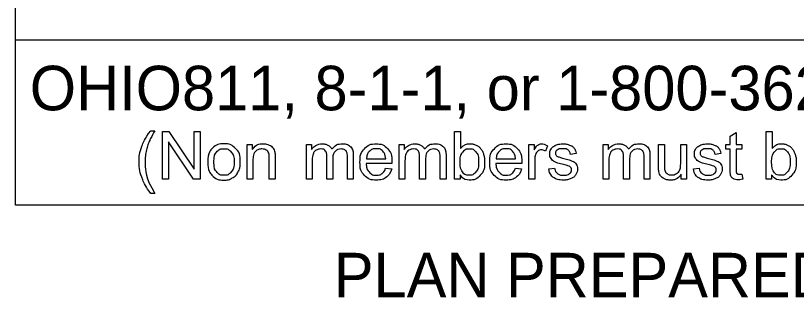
# Model space of a CAD drawing. Extents: x 0 to 2329303, y 0 to 694397.
# Drawn here: x 3 to 5.454, y 2.68 to 3.565 of the extents above; entities that cross this region are included whole.
import ezdxf

# ---------------------------------------------------------------- set-up
doc = ezdxf.new("R2010")
doc.units = 0
doc.layers.add('SH_Data', color=7, linetype='Continuous')

msp = doc.modelspace()

# ---------------------------------------------------------------- linework, layer by layer
at = {"layer": 'SH_Data'}
for p, q in [((3, 2.97), (3, 5.3075)), ((7.25, 3.4878), (3, 3.4878)), ((7.25, 2.97), (3, 2.97))]:
    msp.add_line(p, q, dxfattribs=at)
for points in [[(3.4246, 3.2038), (3.4378, 3.2038)], [(3.4614, 3.0511), (3.4614, 3.2013), (3.4817, 3.2013), (3.5607, 3.0833), (3.5607, 3.2013), (3.5797, 3.2013), (3.5797, 3.0511), (3.5594, 3.0511), (3.4804, 3.169), (3.4804, 3.0511), (3.4614, 3.0511)], [(4.3968, 3.0511), (4.3798, 3.0511), (4.3798, 3.2013), (4.3982, 3.2013), (4.3982, 3.1477)], [(5.2458, 3.083), (5.2458, 3.1456), (5.2321, 3.1456), (5.2321, 3.1599), (5.2458, 3.1599), (5.2458, 3.1869), (5.2642, 3.1979), (5.2642, 3.1599), (5.2826, 3.1599), (5.2826, 3.1456), (5.2642, 3.1456), (5.2642, 3.0819)], [(5.3759, 3.0511), (5.3588, 3.0511), (5.3588, 3.2013), (5.3773, 3.2013), (5.3773, 3.1477)], [(3.7273, 3.0511), (3.7273, 3.1599), (3.7439, 3.1599), (3.7439, 3.1445)], [(3.9137, 3.0511), (3.9137, 3.1599), (3.9302, 3.1599), (3.9302, 3.1446)], [(4.2051, 3.0511), (4.2051, 3.1599), (4.2216, 3.1599), (4.2216, 3.1446)], [(4.6129, 3.0511), (4.6129, 3.1599), (4.6295, 3.1599), (4.6295, 3.1434)], [(4.6719, 3.1565), (4.6655, 3.1394)], [(4.8461, 3.0511), (4.8461, 3.1599), (4.8626, 3.1599), (4.8626, 3.1446)], [(5.0204, 3.0925), (5.0204, 3.1599), (5.0388, 3.1599), (5.0388, 3.0996)], [(5.0901, 3.1017), (5.0901, 3.1599), (5.1085, 3.1599), (5.1085, 3.0511), (5.0921, 3.0511)], [(3.8157, 3.118), (3.8157, 3.0511), (3.7973, 3.0511), (3.7973, 3.1172)], [(3.9968, 3.1143), (3.9968, 3.0511), (3.9784, 3.0511), (3.9784, 3.1217)], [(4.0613, 3.1258), (4.0613, 3.0511), (4.0428, 3.0511), (4.0428, 3.1196)], [(4.2882, 3.1143), (4.2882, 3.0511), (4.2698, 3.0511), (4.2698, 3.1217)], [(4.3526, 3.1258), (4.3526, 3.0511), (4.3342, 3.0511), (4.3342, 3.1196)], [(4.7619, 3.1318), (4.7438, 3.1294)], [(4.9292, 3.1143), (4.9292, 3.0511), (4.9108, 3.0511), (4.9108, 3.1217)], [(4.9936, 3.1258), (4.9936, 3.0511), (4.9752, 3.0511), (4.9752, 3.1196)], [(5.2165, 3.1318), (5.1984, 3.1294)], [(3.7458, 3.1105), (3.7458, 3.0511), (3.7273, 3.0511)], [(3.9322, 3.1075), (3.9322, 3.0511), (3.9137, 3.0511)], [(4.1825, 3.1008), (4.1013, 3.1008)], [(4.1024, 3.1159), (4.1631, 3.1159)], [(4.2235, 3.1075), (4.2235, 3.0511), (4.2051, 3.0511)], [(4.5905, 3.1008), (4.5093, 3.1008)], [(4.5103, 3.1159), (4.5711, 3.1159)], [(4.6313, 3.1081), (4.6313, 3.0511), (4.6129, 3.0511)], [(4.8645, 3.1075), (4.8645, 3.0511), (4.8461, 3.0511)], [(4.1629, 3.0862), (4.182, 3.0838)], [(4.5709, 3.0862), (4.59, 3.0838)], [(4.6755, 3.0836), (4.6937, 3.0865)], [(5.1301, 3.0836), (5.1483, 3.0865)], [(5.2826, 3.0675), (5.2852, 3.0512)], [(4.3968, 3.0647), (4.3968, 3.0511)], [(5.0921, 3.0511), (5.0921, 3.0672)], [(5.3759, 3.0647), (5.3759, 3.0511)], [(3.4378, 3.0069), (3.4246, 3.0069)]]:
    msp.add_lwpolyline(points, dxfattribs=at)
for points in [[(3.4246, 3.0069), (3.4093, 3.0262), (3.3988, 3.052), (3.3882, 3.0778), (3.3882, 3.1054), (3.3882, 3.1298), (3.3961, 3.1522), (3.4053, 3.1781), (3.4246, 3.2038)], [(3.4378, 3.2038), (3.4254, 3.1825), (3.4214, 3.1734), (3.4152, 3.1592), (3.4116, 3.1439), (3.4072, 3.1247), (3.4072, 3.1053), (3.4072, 3.0561), (3.4378, 3.0069)], [(3.6038, 3.1055), (3.6038, 3.1357), (3.6206, 3.1503), (3.6347, 3.1623), (3.6548, 3.1623), (3.6772, 3.1623), (3.6915, 3.1476), (3.7057, 3.133), (3.7057, 3.1071), (3.7057, 3.0861), (3.6994, 3.074), (3.6931, 3.062), (3.6811, 3.0554), (3.669, 3.0487), (3.6548, 3.0487), (3.632, 3.0487), (3.6179, 3.0633), (3.6038, 3.078), (3.6038, 3.1055)], [(3.6228, 3.1055), (3.6228, 3.0846), (3.6319, 3.0742), (3.641, 3.0638), (3.6548, 3.0638), (3.6685, 3.0638), (3.6776, 3.0743), (3.6867, 3.0847), (3.6867, 3.1061), (3.6867, 3.1263), (3.6776, 3.1367), (3.6684, 3.1471), (3.6548, 3.1471), (3.641, 3.1471), (3.6319, 3.1368), (3.6228, 3.1264), (3.6228, 3.1055)], [(3.7439, 3.1445), (3.7559, 3.1623), (3.7785, 3.1623), (3.7883, 3.1623), (3.7966, 3.1588), (3.8048, 3.1553), (3.8089, 3.1495), (3.813, 3.1438), (3.8147, 3.1359), (3.8157, 3.1308), (3.8157, 3.118)], [(3.7973, 3.1172), (3.7973, 3.1285), (3.7951, 3.1341), (3.7929, 3.1397), (3.7875, 3.143), (3.782, 3.1463), (3.7746, 3.1463), (3.7628, 3.1463), (3.7543, 3.1388), (3.7458, 3.1314), (3.7458, 3.1105)], [(3.9302, 3.1446), (3.9353, 3.1526), (3.9438, 3.1575), (3.9523, 3.1623), (3.9632, 3.1623), (3.9753, 3.1623), (3.983, 3.1573), (3.9908, 3.1523), (3.994, 3.1432), (4.0069, 3.1623), (4.0276, 3.1623), (4.0438, 3.1623), (4.0525, 3.1534), (4.0613, 3.1444), (4.0613, 3.1258)], [(3.9784, 3.1217), (3.9784, 3.134), (3.9739, 3.1402), (3.9694, 3.1463), (3.9591, 3.1463), (3.9513, 3.1463), (3.9447, 3.1422), (3.9381, 3.1381), (3.9351, 3.1302), (3.9322, 3.1224), (3.9322, 3.1075)], [(4.0428, 3.1196), (4.0428, 3.1307), (4.041, 3.1355), (4.0392, 3.1404), (4.0345, 3.1433), (4.0298, 3.1463), (4.0235, 3.1463), (4.012, 3.1463), (4.0044, 3.1387), (3.9968, 3.1311), (3.9968, 3.1143)], [(4.182, 3.0838), (4.1775, 3.0671), (4.1653, 3.0579), (4.1531, 3.0487), (4.1341, 3.0487), (4.1103, 3.0487), (4.0963, 3.0634), (4.0823, 3.0781), (4.0823, 3.1046), (4.0823, 3.132), (4.0965, 3.1472), (4.1106, 3.1623), (4.1331, 3.1623), (4.1549, 3.1623), (4.1688, 3.1475), (4.1826, 3.1326), (4.1826, 3.1057), (4.1826, 3.104), (4.1825, 3.1008)], [(4.1631, 3.1159), (4.1619, 3.1297), (4.1562, 3.1365), (4.1473, 3.1472), (4.1333, 3.1472), (4.1206, 3.1472), (4.1119, 3.1387), (4.1033, 3.1302), (4.1024, 3.1159)], [(4.2216, 3.1446), (4.2267, 3.1526), (4.2352, 3.1575), (4.2437, 3.1623), (4.2546, 3.1623), (4.2667, 3.1623), (4.2744, 3.1573), (4.2821, 3.1523), (4.2853, 3.1432), (4.2983, 3.1623), (4.319, 3.1623), (4.3352, 3.1623), (4.3439, 3.1534), (4.3526, 3.1444), (4.3526, 3.1258)], [(4.2698, 3.1217), (4.2698, 3.134), (4.2653, 3.1402), (4.2607, 3.1463), (4.2505, 3.1463), (4.2427, 3.1463), (4.2361, 3.1422), (4.2295, 3.1381), (4.2265, 3.1302), (4.2235, 3.1224), (4.2235, 3.1075)], [(4.3342, 3.1196), (4.3342, 3.1307), (4.3324, 3.1355), (4.3306, 3.1404), (4.3259, 3.1433), (4.3212, 3.1463), (4.3148, 3.1463), (4.3034, 3.1463), (4.2958, 3.1387), (4.2882, 3.1311), (4.2882, 3.1143)], [(4.3966, 3.1063), (4.3966, 3.0868), (4.4019, 3.0781), (4.4106, 3.0638), (4.4254, 3.0638), (4.4375, 3.0638), (4.4463, 3.0743), (4.4551, 3.0848), (4.4551, 3.1056), (4.4551, 3.1269), (4.4466, 3.1371), (4.4382, 3.1472), (4.4262, 3.1472), (4.4142, 3.1472), (4.4054, 3.1367), (4.3966, 3.1262), (4.3966, 3.1063)], [(4.3982, 3.1477), (4.4099, 3.1623), (4.428, 3.1623), (4.438, 3.1623), (4.447, 3.1583), (4.4559, 3.1543), (4.4617, 3.1469), (4.4675, 3.1396), (4.4708, 3.1293), (4.4741, 3.1189), (4.4741, 3.1072), (4.4741, 3.0792), (4.4602, 3.064), (4.4464, 3.0487), (4.427, 3.0487), (4.4078, 3.0487), (4.3968, 3.0647)], [(4.59, 3.0838), (4.5855, 3.0671), (4.5733, 3.0579), (4.5611, 3.0487), (4.5421, 3.0487), (4.5183, 3.0487), (4.5043, 3.0634), (4.4903, 3.0781), (4.4903, 3.1046), (4.4903, 3.132), (4.5045, 3.1472), (4.5186, 3.1623), (4.5411, 3.1623), (4.5629, 3.1623), (4.5767, 3.1475), (4.5906, 3.1326), (4.5906, 3.1057), (4.5906, 3.104), (4.5905, 3.1008)], [(4.5711, 3.1159), (4.5699, 3.1297), (4.5641, 3.1365), (4.5553, 3.1472), (4.5413, 3.1472), (4.5286, 3.1472), (4.5199, 3.1387), (4.5113, 3.1302), (4.5103, 3.1159)], [(4.6295, 3.1434), (4.6358, 3.155), (4.6412, 3.1587), (4.6466, 3.1623), (4.653, 3.1623), (4.6623, 3.1623), (4.6719, 3.1565)], [(4.6655, 3.1394), (4.6588, 3.1433), (4.652, 3.1433), (4.646, 3.1433), (4.6412, 3.1397), (4.6364, 3.1361), (4.6344, 3.1296), (4.6313, 3.1198), (4.6313, 3.1081)], [(4.7438, 3.1294), (4.7426, 3.1378), (4.7367, 3.1425), (4.7308, 3.1472), (4.72, 3.1472), (4.7073, 3.1472), (4.7019, 3.143), (4.6964, 3.1388), (4.6964, 3.1332), (4.6964, 3.1296), (4.6987, 3.1267), (4.7009, 3.1237), (4.7058, 3.1218), (4.7085, 3.1208), (4.7221, 3.1171), (4.7417, 3.1118), (4.7494, 3.1085), (4.7572, 3.1052), (4.7616, 3.0988), (4.766, 3.0925), (4.766, 3.0831), (4.766, 3.0739), (4.7606, 3.0657), (4.7552, 3.0576), (4.7451, 3.0532), (4.7349, 3.0487), (4.7221, 3.0487), (4.7008, 3.0487), (4.6897, 3.0575), (4.6786, 3.0663), (4.6755, 3.0836)], [(4.6937, 3.0865), (4.6952, 3.0755), (4.7023, 3.0696), (4.7093, 3.0638), (4.7219, 3.0638), (4.7347, 3.0638), (4.7409, 3.069), (4.747, 3.0742), (4.747, 3.0811), (4.747, 3.0874), (4.7416, 3.091), (4.7378, 3.0935), (4.7227, 3.0972), (4.7024, 3.1024), (4.6945, 3.1061), (4.6867, 3.1098), (4.6826, 3.1164), (4.6786, 3.123), (4.6786, 3.131), (4.6786, 3.1383), (4.6819, 3.1445), (4.6853, 3.1507), (4.691, 3.1548), (4.6953, 3.1579), (4.7027, 3.1601), (4.7102, 3.1623), (4.7187, 3.1623), (4.7315, 3.1623), (4.7412, 3.1586), (4.7509, 3.155), (4.7555, 3.1487), (4.7602, 3.1423), (4.7619, 3.1318)], [(4.8626, 3.1446), (4.8677, 3.1526), (4.8762, 3.1575), (4.8847, 3.1623), (4.8956, 3.1623), (4.9077, 3.1623), (4.9154, 3.1573), (4.9231, 3.1523), (4.9263, 3.1432), (4.9393, 3.1623), (4.96, 3.1623), (4.9762, 3.1623), (4.9849, 3.1534), (4.9936, 3.1444), (4.9936, 3.1258)], [(4.9108, 3.1217), (4.9108, 3.134), (4.9063, 3.1402), (4.9017, 3.1463), (4.8915, 3.1463), (4.8837, 3.1463), (4.8771, 3.1422), (4.8705, 3.1381), (4.8675, 3.1302), (4.8645, 3.1224), (4.8645, 3.1075)], [(4.9752, 3.1196), (4.9752, 3.1307), (4.9734, 3.1355), (4.9716, 3.1404), (4.9669, 3.1433), (4.9622, 3.1463), (4.9558, 3.1463), (4.9444, 3.1463), (4.9368, 3.1387), (4.9292, 3.1311), (4.9292, 3.1143)], [(5.1984, 3.1294), (5.1972, 3.1378), (5.1913, 3.1425), (5.1854, 3.1472), (5.1746, 3.1472), (5.1619, 3.1472), (5.1564, 3.143), (5.151, 3.1388), (5.151, 3.1332), (5.151, 3.1296), (5.1533, 3.1267), (5.1555, 3.1237), (5.1603, 3.1218), (5.1631, 3.1208), (5.1766, 3.1171), (5.1962, 3.1118), (5.204, 3.1085), (5.2117, 3.1052), (5.2162, 3.0988), (5.2206, 3.0925), (5.2206, 3.0831), (5.2206, 3.0739), (5.2152, 3.0657), (5.2098, 3.0576), (5.1996, 3.0532), (5.1895, 3.0487), (5.1767, 3.0487), (5.1554, 3.0487), (5.1443, 3.0575), (5.1331, 3.0663), (5.1301, 3.0836)], [(5.1483, 3.0865), (5.1498, 3.0755), (5.1568, 3.0696), (5.1639, 3.0638), (5.1765, 3.0638), (5.1893, 3.0638), (5.1954, 3.069), (5.2016, 3.0742), (5.2016, 3.0811), (5.2016, 3.0874), (5.1961, 3.091), (5.1923, 3.0935), (5.1773, 3.0972), (5.157, 3.1024), (5.1491, 3.1061), (5.1413, 3.1098), (5.1372, 3.1164), (5.1332, 3.123), (5.1332, 3.131), (5.1332, 3.1383), (5.1365, 3.1445), (5.1398, 3.1507), (5.1456, 3.1548), (5.1499, 3.1579), (5.1573, 3.1601), (5.1648, 3.1623), (5.1733, 3.1623), (5.1861, 3.1623), (5.1958, 3.1586), (5.2055, 3.155), (5.2101, 3.1487), (5.2147, 3.1423), (5.2165, 3.1318)], [(5.3757, 3.1063), (5.3757, 3.0868), (5.381, 3.0781), (5.3897, 3.0638), (5.4045, 3.0638), (5.4166, 3.0638), (5.4253, 3.0743), (5.4341, 3.0848), (5.4341, 3.1056), (5.4341, 3.1269), (5.4257, 3.1371), (5.4173, 3.1472), (5.4053, 3.1472), (5.3932, 3.1472), (5.3844, 3.1367), (5.3757, 3.1262), (5.3757, 3.1063)], [(5.3773, 3.1477), (5.3889, 3.1623), (5.4071, 3.1623), (5.4171, 3.1623), (5.426, 3.1583), (5.435, 3.1543), (5.4408, 3.1469), (5.4466, 3.1396), (5.4499, 3.1293), (5.4531, 3.1189), (5.4531, 3.1072), (5.4531, 3.0792), (5.4393, 3.064), (5.4255, 3.0487), (5.4061, 3.0487), (5.3868, 3.0487), (5.3759, 3.0647)], [(4.1013, 3.1008), (4.1024, 3.0829), (4.1115, 3.0733), (4.1206, 3.0638), (4.1342, 3.0638), (4.1444, 3.0638), (4.1515, 3.0692), (4.1587, 3.0745), (4.1629, 3.0862)], [(4.5093, 3.1008), (4.5103, 3.0829), (4.5195, 3.0733), (4.5286, 3.0638), (4.5422, 3.0638), (4.5524, 3.0638), (4.5595, 3.0692), (4.5667, 3.0745), (4.5709, 3.0862)], [(5.0921, 3.0672), (5.0794, 3.0487), (5.0576, 3.0487), (5.048, 3.0487), (5.0396, 3.0524), (5.0313, 3.0561), (5.0272, 3.0617), (5.0232, 3.0672), (5.0215, 3.0753), (5.0204, 3.0808), (5.0204, 3.0925)], [(5.0388, 3.0996), (5.0388, 3.0852), (5.04, 3.0802), (5.0417, 3.0729), (5.0473, 3.0688), (5.053, 3.0646), (5.0613, 3.0646), (5.0695, 3.0646), (5.0768, 3.0689), (5.0841, 3.0731), (5.0871, 3.0804), (5.0901, 3.0877), (5.0901, 3.1017)], [(5.2852, 3.0512), (5.2775, 3.0496), (5.2713, 3.0496), (5.2613, 3.0496), (5.2558, 3.0528), (5.2503, 3.056), (5.248, 3.0612), (5.2458, 3.0663), (5.2458, 3.083)], [(5.2642, 3.0819), (5.2642, 3.074), (5.2652, 3.0717), (5.2661, 3.0694), (5.2683, 3.0681), (5.2705, 3.0668), (5.2746, 3.0668), (5.2776, 3.0668), (5.2826, 3.0675)]]:
    msp.add_open_spline(points, degree=3, dxfattribs=at)

# ---------------------------------------------------------------- texts
for s, p in [('OHIO811, 8-1-1, or 1-800-362-2764', (3.0445, 3.2678)), ('PLAN PREPARED BY:', (4.0001, 2.68))]:
    msp.add_text(s, height=0.14, dxfattribs=at).set_placement(p)

doc.saveas('drawing.dxf')
